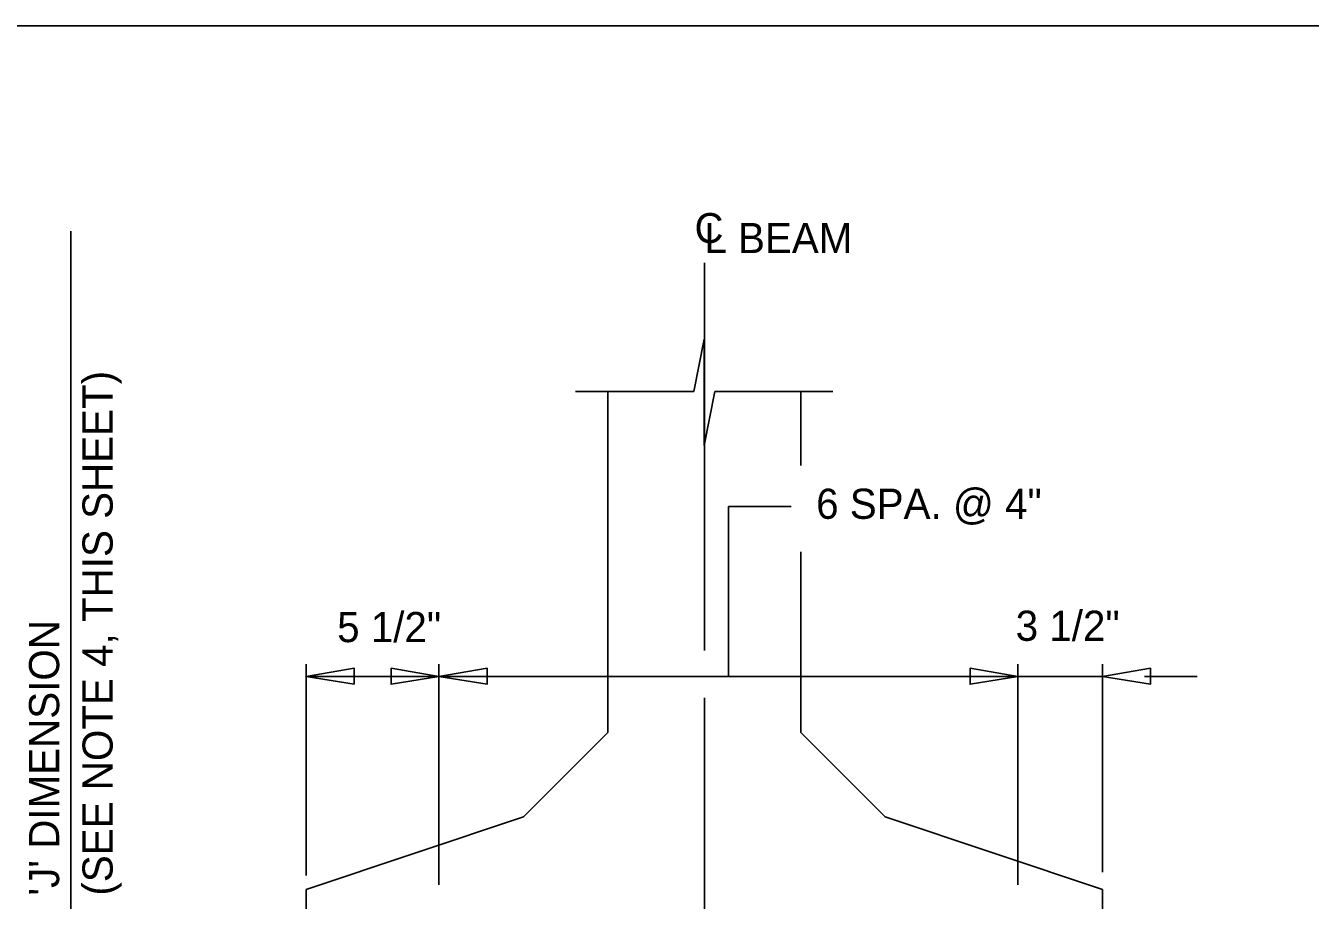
# Model space of a CAD drawing. Extents: x 639980 to 641204, y 298038 to 300414.
# Drawn here: x 640087.9 to 640215.7, y 298529.8 to 298616.8 of the extents above; entities that cross this region are included whole.
import ezdxf

# ---------------------------------------------------------------- set-up
doc = ezdxf.new("R2010")
doc.units = 0
doc.layers.add('2', color=7, linetype='Continuous')

msp = doc.modelspace()

# ---------------------------------------------------------------- linework, layer by layer
at = {"layer": '2'}
for p, q in [((640020.31, 298616.78), (640806.31, 298616.78)), ((640092.37, 298527.94), (640092.37, 298596.34)), ((640155.4, 298554.67), (640155.4, 298593.21)), ((640155.38, 298585.61), (640154.34, 298580.41)), ((640155.38, 298585.61), (640155.38, 298575.05)), ((640142.58, 298580.41), (640154.34, 298580.41)), ((640145.8, 298580.41), (640145.8, 298546.51)), ((640156.45, 298580.41), (640155.38, 298575.05)), ((640156.42, 298580.41), (640168.18, 298580.41)), ((640165, 298580.41), (640165, 298573.06)), ((640157.8, 298552.09), (640157.8, 298568.97)), ((640164.02, 298568.97), (640157.8, 298568.97)), ((640165, 298564.48), (640165, 298546.51)), ((640115.79, 298532.28), (640115.79, 298553.29)), ((640128.99, 298531.35), (640128.99, 298553.29)), ((640186.6, 298531.35), (640186.6, 298553.29)), ((640195, 298532.63), (640195, 298553.29)), ((640115.79, 298552.09), (640128.99, 298552.09)), ((640128.99, 298552.09), (640186.6, 298552.09)), ((640186.6, 298552.09), (640195, 298552.09)), ((640204.44, 298552.09), (640199.18, 298552.09)), ((640155.4, 298502.27), (640155.4, 298549.94)), ((640145.8, 298546.51), (640137.39, 298538.11)), ((640165, 298546.51), (640173.4, 298538.11)), ((640137.39, 298538.11), (640115.79, 298530.91)), ((640173.4, 298538.11), (640195, 298530.91)), ((640115.79, 298530.91), (640115.79, 298511.1)), ((640195, 298530.91), (640195, 298511.1))]:
    msp.add_line(p, q, dxfattribs=at)
for points in [[(640120.56, 298551.3), (640115.79, 298552.09), (640120.56, 298552.89)], [(640124.22, 298552.89), (640128.99, 298552.09), (640124.22, 298551.3)], [(640133.77, 298552.89), (640128.99, 298552.09), (640133.77, 298551.3)], [(640181.83, 298552.89), (640186.6, 298552.09), (640181.83, 298551.3)], [(640199.78, 298552.89), (640195, 298552.09), (640199.78, 298551.3)]]:
    msp.add_lwpolyline(points, close=True, dxfattribs=at)

# ---------------------------------------------------------------- texts
for s, height, p in [('C', 2.97, (640154.42, 298595.18)), ('L BEAM', 3, (640155.4, 298594.17)), ('6 SPA. @ 4"', 3.0005, (640166.52, 298567.75)), ('5 1/2"', 3.001, (640118.86, 298555.49)), ('3 1/2"', 3.001, (640186.37, 298555.62))]:
    msp.add_text(s, height=height, dxfattribs=at).set_placement(p)
for s, p in [('(SEE NOTE 4, THIS SHEET)', (640096.52, 298530.29)), ("'J' DIMENSION", (640091.2, 298530.29))]:
    msp.add_text(s, height=3.0005, rotation=90, dxfattribs=at).set_placement(p)

doc.saveas('drawing.dxf')
